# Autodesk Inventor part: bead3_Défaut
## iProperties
Shininess: 64.0
Length Units: 11269
Angle Units: 11279
Time Units: 11290
Mass Units: 11283
Length Display Precision: 3
Angle Display Precision: 2
Compacted: True
Part Number: bead3_Défaut
Document SubType Name: Modeling
Created: 2006-11
Material: Par défaut
Designer: profs_sti
Density: 0.0
Volumn: 0.0
Area: 0.0
PropertySet Name: Model Information
Control State: 0
Master: False
Checked Out: False
Author: profs_sti
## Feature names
1. Base1
